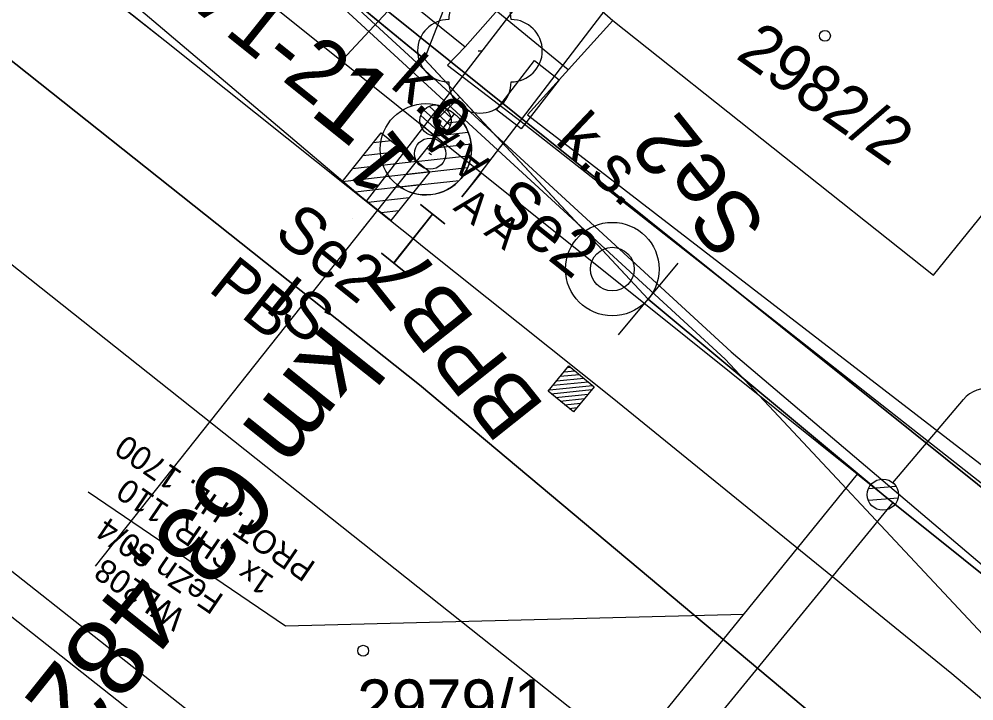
# Model space of a CAD drawing. Extents: x -620537 to -620023, y -1122866 to -1122384.
# Drawn here: x -620241.34 to -620210.72, y -1122748.65 to -1122726.78 of the extents above; entities that cross this region are included whole.
import ezdxf

# ---------------------------------------------------------------- set-up
doc = ezdxf.new("R2010")
doc.units = 0
for name, color, linetype in [('060603_ROZVODY_NN', 7, 'Continuous'), ('060604_ROZVODY_SEE', 7, 'Continuous'), ('CETIN', 7, 'Continuous'), ('POPIS KABELOVÉ TRASY', 7, 'Continuous'), ('PS 06-14-01_trasa_sdělovací_nové', 7, 'Continuous'), ('SEE', 7, 'Continuous'), ('SSZT', 7, 'Continuous'), ('SSZT-DK', 7, 'Continuous'), ('SSZT-TK', 7, 'Continuous'), ('STÁVAJÍCÍ STOŽÁRY ODHAD', 7, 'Continuous'), ('UZEMNĚNÍ', 7, 'Continuous'), ('Vrstva 1', 7, 'Continuous'), ('Vrstva 16', 7, 'Continuous'), ('Vrstva 2', 7, 'Continuous'), ('Vrstva 27', 7, 'Continuous'), ('Vrstva 3', 7, 'Continuous'), ('Vrstva 36', 7, 'Continuous'), ('Vrstva 50', 7, 'Continuous'), ('Vrstva 53', 7, 'Continuous'), ('Vrstva 55', 7, 'Continuous'), ('Vrstva 56', 7, 'Continuous'), ('Vrstva 57', 7, 'Continuous'), ('Vrstva 6', 7, 'Continuous'), ('Vrstva 62', 7, 'Continuous'), ('ČD-T', 7, 'Continuous')]:
    doc.layers.add(name, color=color, linetype=linetype)

msp = doc.modelspace()

# ---------------------------------------------------------------- linework, layer by layer
at = {"layer": '060603_ROZVODY_NN'}
msp.add_lwpolyline([(-620240.174, -1122718.342), (-620228.339, -1122728.069), (-620221.166, -1122735.76), (-620213.633, -1122742.038), (-620205.954, -1122748.188), (-620177.512, -1122774.524), (-620185.522, -1122781.049), (-620181.59, -1122785.57), (-620173.131, -1122796.401), (-620158.909, -1122820.61), (-620158.907, -1122820.615)], dxfattribs=at)
at = {"layer": '060604_ROZVODY_SEE'}
msp.add_lwpolyline([(-620176.843, -1122775.143), (-620205.954, -1122748.188), (-620213.633, -1122742.038), (-620221.166, -1122735.76), (-620228.339, -1122728.069), (-620234.256, -1122723.205), (-620240.174, -1122718.342), (-620248.298, -1122711.665), (-620253.571, -1122707.331), (-620257.271, -1122704.364), (-620247.325, -1122692.032), (-620244.518, -1122694.296)], dxfattribs=at)
at = {"layer": 'CETIN'}
for points in [[(-620281.95, -1122736.09), (-620279.78, -1122731.91), (-620278.12, -1122730.04), (-620275.23, -1122726.8), (-620267.96, -1122716.51), (-620253.8, -1122706.08), (-620234.3, -1122721.82), (-620227.04, -1122727.67)], [(-620227.04, -1122727.67), (-620224.61, -1122724.91)], [(-620227.04, -1122727.67), (-620227.6, -1122728.26), (-620225.24, -1122730.07), (-620192.39, -1122755.87), (-620182.03, -1122766.47), (-620178.55, -1122770.03), (-620178.11, -1122770.48), (-620151.688, -1122809.986)]]:
    msp.add_lwpolyline(points, dxfattribs=at)
at = {"layer": 'POPIS KABELOVÉ TRASY'}
msp.add_line((-620239.125, -1122741.959), (-620239.125, -1122741.959), dxfattribs=at)
msp.add_line((-620239.125, -1122741.959), (-620239.125, -1122741.959), dxfattribs=at)
for points in [[(-620228.339, -1122728.069), (-620218.049, -1122701.604), (-620224.371, -1122697.311)], [(-620218.104, -1122745.872), (-620232.802, -1122746.253), (-620239.125, -1122741.959)]]:
    msp.add_lwpolyline(points, dxfattribs=at)
at = {"layer": 'PS 06-14-01_trasa_sdělovací_nové'}
msp.add_lwpolyline([(-620232.134, -1122718.841), (-620235.045, -1122722.562), (-620243.025, -1122715.998), (-620248.321, -1122722.765), (-620228.504, -1122738.508), (-620211.634, -1122752.654), (-620198.933, -1122763.626), (-620190.05, -1122772.28), (-620190.33, -1122775.52), (-620181.59, -1122785.57), (-620173.131, -1122796.401), (-620158.909, -1122820.61), (-620158.907, -1122820.615)], dxfattribs=at)
at = {"layer": 'SEE'}
for points in [[(-620257.826, -1122706.644), (-620244.955, -1122716.952), (-620221.313, -1122735.887), (-620205.954, -1122748.188), (-620187.818, -1122764.98), (-620176.843, -1122775.143)], [(-620213.321, -1122742.288), (-620221.898, -1122752.771), (-620210.905, -1122762.159)]]:
    msp.add_lwpolyline(points, dxfattribs=at)
at = {"layer": 'SSZT'}
msp.add_lwpolyline([(-620153.29, -1122812.344), (-620160.216, -1122801.593), (-620175.654, -1122778.856), (-620179.825, -1122771.902), (-620189.291, -1122760.708), (-620207.424, -1122744.252), (-620237.066, -1122720.469), (-620255.602, -1122705.516), (-620251.355, -1122700.201)], dxfattribs=at)
at = {"layer": 'SSZT-DK'}
msp.add_lwpolyline([(-620332.62, -1122702.617), (-620308.772, -1122717.798), (-620291.405, -1122732.208), (-620277.196, -1122744.115), (-620257.608, -1122720.05), (-620250.251, -1122710.721), (-620233.29, -1122724.26), (-620218.699, -1122737.685), (-620210.438, -1122746.518), (-620193.319, -1122761.993), (-620178.352, -1122775.894), (-620171.184, -1122783.621), (-620164.843, -1122792.284), (-620156.695, -1122803.312), (-620151.985, -1122810.422)], dxfattribs=at)
at = {"layer": 'SSZT-TK'}
msp.add_line((-620229.519, -1122726.524), (-620231.426, -1122728.569), dxfattribs=at)
msp.add_lwpolyline([(-620251.547, -1122700.3), (-620255.602, -1122705.516), (-620237.066, -1122720.469), (-620207.424, -1122744.252), (-620189.291, -1122760.708), (-620179.825, -1122771.902), (-620175.654, -1122778.856), (-620160.216, -1122801.593), (-620153.29, -1122812.344)], dxfattribs=at)
at = {"layer": 'STÁVAJÍCÍ STOŽÁRY ODHAD'}
for p, q in [((-620213.319, -1122741.653), (-620211.057, -1122738.981)), ((-620214.101, -1122741.837), (-620213.224, -1122741.764)), ((-620214.106, -1122742.213), (-620213.152, -1122742.134))]:
    msp.add_line(p, q, dxfattribs=at)
msp.add_circle((-620213.642, -1122742.034), 0.5, dxfattribs=at)
msp.add_arc((-620210.294, -1122739.627), 1, 319.7483, 139.7483, dxfattribs=at)
at = {"layer": 'UZEMNĚNÍ'}
msp.add_lwpolyline([(-620221.747, -1122750.368), (-620214.46, -1122741.375), (-620205.954, -1122748.188), (-620176.843, -1122775.143)], dxfattribs=at)
at = {"layer": 'Vrstva 1'}
for p, q in [((-620227.989, -1122730.033), (-620227.205, -1122729.285)), ((-620227.205, -1122729.285), (-620221.166, -1122735.76))]:
    msp.add_line(p, q, dxfattribs=at)
for points in [[(-620307.469, -1122665.582), (-620307.245, -1122665.745), (-620300.366, -1122670.953), (-620293.063, -1122676.601), (-620287.47, -1122681.018), (-620281.24, -1122686.066), (-620276.174, -1122690.251), (-620272.417, -1122693.451), (-620267.757, -1122697.544), (-620266.519, -1122698.689), (-620262.242, -1122702.65), (-620256.103, -1122708.562), (-620249.907, -1122714.621), (-620245.657, -1122718.815), (-620238.557, -1122725.547), (-620230.199, -1122732.623), (-620229.854, -1122732.906)], [(-620310.211, -1122669.621), (-620307.461, -1122671.648), (-620300.906, -1122676.615), (-620294.546, -1122681.556), (-620287.988, -1122686.712), (-620281.909, -1122691.52), (-620277.852, -1122694.735), (-620274.362, -1122697.517), (-620269.944, -1122701.034), (-620263.761, -1122705.928), (-620255.894, -1122712.191), (-620251.107, -1122715.999), (-620247.589, -1122718.79), (-620245.37, -1122720.556), (-620245.065, -1122720.798), (-620243.16, -1122722.318), (-620236.673, -1122727.474), (-620229.854, -1122732.906), (-620228.705, -1122733.823), (-620228.351, -1122734.106), (-620222.324, -1122738.923)], [(-620287.988, -1122686.712), (-620281.909, -1122691.52), (-620277.852, -1122694.735), (-620274.362, -1122697.517), (-620269.944, -1122701.034), (-620263.761, -1122705.928), (-620255.894, -1122712.191), (-620251.107, -1122715.999), (-620247.589, -1122718.79), (-620245.37, -1122720.556), (-620245.065, -1122720.798), (-620243.16, -1122722.318), (-620236.673, -1122727.474), (-620229.854, -1122732.906), (-620228.705, -1122733.823), (-620228.351, -1122734.106), (-620222.324, -1122738.923), (-620215.936, -1122744.099), (-620211.427, -1122747.773), (-620209.034, -1122749.786), (-620203.242, -1122754.772), (-620197.369, -1122760.098), (-620191.907, -1122765.364)], [(-620173.839, -1122795.494), (-620176.67, -1122791.87), (-620181.59, -1122785.57), (-620185.43, -1122781.13), (-620190.33, -1122775.52), (-620190.05, -1122772.28), (-620198.933, -1122763.626), (-620211.634, -1122752.654), (-620228.504, -1122738.508), (-620248.321, -1122722.765)], [(-620235.055, -1122722.549), (-620228.339, -1122728.069), (-620227.205, -1122729.285)]]:
    msp.add_lwpolyline(points, dxfattribs=at)
at = {"layer": 'Vrstva 16'}
msp.add_lwpolyline([(-620223.739, -1122728.414), (-620230.921, -1122722.506), (-620236.041, -1122718.293), (-620237.607, -1122717.084), (-620236.205, -1122715.408), (-620251.701, -1122703.411), (-620251.364, -1122702.889), (-620249.497, -1122700.283), (-620232.51, -1122713.28), (-620235.025, -1122716.425), (-620234.751, -1122716.645), (-620225.938, -1122723.731)], dxfattribs=at)
at = {"layer": 'Vrstva 2'}
for p, q in [((-620227.517, -1122730.191), (-620228.194, -1122729.578)), ((-620227.5, -1122729.937), (-620227.942, -1122729.537)), ((-620227.384, -1122729.816), (-620229.212, -1122732.102)), ((-620227.786, -1122730.488), (-620228.462, -1122729.875)), ((-620227.619, -1122730.369), (-620228.359, -1122729.699)), ((-620228.037, -1122730.529), (-620228.478, -1122730.13)), ((-620227.623, -1122730.111), (-620227.149, -1122730.058)), ((-620227.954, -1122730.526), (-620226.945, -1122730.414)), ((-620228.285, -1122730.94), (-620226.85, -1122730.78)), ((-620228.618, -1122731.354), (-620226.852, -1122731.157)), ((-620228.949, -1122731.768), (-620226.963, -1122731.547)), ((-620229.121, -1122732.165), (-620227.234, -1122731.955)), ((-620229.212, -1122732.102), (-620229.854, -1122732.906)), ((-620229.854, -1122732.906), (-620238.907, -1122744.323)), ((-620222.125, -1122736.913), (-620220.207, -1122734.607)), ((-620223.868, -1122738.095), (-620223.523, -1122738.061)), ((-620223.75, -1122737.951), (-620223.667, -1122737.943)), ((-620224.221, -1122738.526), (-620223.092, -1122738.413)), ((-620224.103, -1122738.382), (-620223.236, -1122738.296)), ((-620223.986, -1122738.238), (-620223.38, -1122738.178)), ((-620224.338, -1122738.669), (-620222.949, -1122738.531)), ((-620224.283, -1122738.796), (-620222.978, -1122738.666)), ((-620224.139, -1122738.913), (-620223.096, -1122738.809)), ((-620223.996, -1122739.031), (-620223.214, -1122738.953)), ((-620223.852, -1122739.148), (-620223.331, -1122739.096)), ((-620223.708, -1122739.266), (-620223.449, -1122739.24))]:
    msp.add_line(p, q, dxfattribs=at)
for points in [[(-620249.907, -1122714.621), (-620245.657, -1122718.815), (-620238.557, -1122725.547), (-620230.199, -1122732.623), (-620229.854, -1122732.906)], [(-620251.107, -1122715.999), (-620247.589, -1122718.79), (-620245.37, -1122720.556), (-620245.065, -1122720.798), (-620243.16, -1122722.318), (-620238.765, -1122725.812), (-620236.673, -1122727.474), (-620229.854, -1122732.906)]]:
    msp.add_lwpolyline(points, dxfattribs=at)
msp.add_lwpolyline([(-620223.713, -1122737.905), (-620222.9, -1122738.571), (-620223.566, -1122739.383), (-620224.378, -1122738.718)], close=True, dxfattribs=at)
msp.add_lwpolyline([(-620223.713, -1122737.905), (-620222.9, -1122738.571), (-620223.566, -1122739.383), (-620224.378, -1122738.718)], close=True, dxfattribs=at)
for centre, radius in [((-620228.298, -1122730.959), 1.464), ((-620227.989, -1122730.033), 0.5), ((-620222.319, -1122734.801), 1.5), ((-620222.319, -1122734.801), 0.7)]:
    msp.add_circle(centre, radius, dxfattribs=at)
msp.add_arc((-620228.298, -1122730.959), 1.463, 231.386, 51.3468, dxfattribs=at)
at = {"layer": 'Vrstva 27'}
msp.add_line((-620228.203, -1122731.073), (-620228.117, -1122731.125), dxfattribs=at)
msp.add_circle((-620228.16, -1122731.099), 0.5, dxfattribs=at)
at = {"layer": 'Vrstva 3'}
for p, q in [((-620230.199, -1122732.623), (-620210.91, -1122707.563)), ((-620229.413, -1122730.691), (-620229.988, -1122730.756)), ((-620228.999, -1122731.022), (-620230.319, -1122731.17)), ((-620228.584, -1122731.353), (-620230.65, -1122731.585)), ((-620228.17, -1122731.684), (-620230.981, -1122731.999)), ((-620228.5, -1122732.098), (-620230.566, -1122732.33)), ((-620228.832, -1122732.513), (-620230.151, -1122732.661)), ((-620229.162, -1122732.927), (-620229.737, -1122732.992)), ((-620228.472, -1122732.73), (-620227.69, -1122733.353)), ((-620227.69, -1122733.354), (-620228.471, -1122732.73)), ((-620228.081, -1122733.041), (-620229.329, -1122734.605)), ((-620229.329, -1122734.604), (-620228.081, -1122733.042)), ((-620228.939, -1122734.916), (-620229.72, -1122734.292)), ((-620229.72, -1122734.293), (-620228.938, -1122734.916))]:
    msp.add_line(p, q, dxfattribs=at)
msp.add_lwpolyline([(-620229.417, -1122733.247), (-620230.981, -1122731.999), (-620229.733, -1122730.436), (-620228.17, -1122731.684)], close=True, dxfattribs=at)
at = {"layer": 'Vrstva 36'}
msp.add_lwpolyline([(-620225.246, -1122730.307), (-620226.036, -1122729.694), (-620224.81, -1122728.113), (-620224.02, -1122728.726), (-620225.246, -1122730.307)], dxfattribs=at)
at = {"layer": 'Vrstva 50'}
msp.add_line((-620226.624, -1122727.801), (-620226.482, -1122727.801), dxfattribs=at)
for centre, start, end in [((-620226.564, -1122726.799), 0, 180), ((-620227.564, -1122727.799), 90, 270), ((-620225.564, -1122727.799), 270, 90), ((-620226.564, -1122728.799), 180, 0)]:
    msp.add_arc(centre, 1, start, end, dxfattribs=at)
at = {"layer": 'Vrstva 53'}
for p, q in [((-620223.68, -1122725.62), (-620222.3, -1122726.83)), ((-620222.3, -1122726.83), (-620225.04, -1122729.85)), ((-620225.04, -1122729.85), (-620205.48, -1122744.93)), ((-620246.12, -1122731.05), (-620221.1, -1122750.9)), ((-620220.43, -1122762.64), (-620252.35, -1122737.47))]:
    msp.add_line(p, q, dxfattribs=at)
at = {"layer": 'Vrstva 55'}
for p, q in [((-620223.68, -1122725.62), (-620222.3, -1122726.83)), ((-620222.3, -1122726.83), (-620225.04, -1122729.85)), ((-620222.3, -1122726.83), (-620212.02, -1122735)), ((-620225.04, -1122729.85), (-620205.48, -1122744.93)), ((-620246.12, -1122731.05), (-620221.1, -1122750.9)), ((-620212.02, -1122735), (-620209.48, -1122731.85)), ((-620220.43, -1122762.64), (-620252.35, -1122737.47))]:
    msp.add_line(p, q, dxfattribs=at)
at = {"layer": 'Vrstva 56'}
msp.add_line((-620225.88, -1122756.88), (-620250.89, -1122737.15), dxfattribs=at)
at = {"layer": 'Vrstva 57'}
for centre in [(-620215.5, -1122727.32), (-620230.31, -1122747.04)]:
    msp.add_circle(centre, 0.175, dxfattribs=at)
at = {"layer": 'Vrstva 6'}
for p, q in [((-620226.831, -1122732.095), (-620209.385, -1122709.263)), ((-620227.143, -1122732.486), (-620226.519, -1122731.704)), ((-620226.519, -1122731.704), (-620227.143, -1122732.486))]:
    msp.add_line(p, q, dxfattribs=at)
at = {"layer": 'Vrstva 62'}
for p, q in [((-620229.734, -1122732.072), (-620229.734, -1122732.072)), ((-620229.418, -1122732.34), (-620229.418, -1122732.34)), ((-620230.659, -1122733.166), (-620230.659, -1122733.166)), ((-620230.307, -1122733.444), (-620230.307, -1122733.444)), ((-620228.274, -1122733.27), (-620228.274, -1122733.27)), ((-620229.185, -1122734.341), (-620229.185, -1122734.341))]:
    msp.add_line(p, q, dxfattribs=at)
at = {"layer": 'ČD-T'}
msp.add_lwpolyline([(-620332.453, -1122702.37), (-620308.585, -1122717.564), (-620291.218, -1122731.973), (-620279.983, -1122741.462), (-620260.482, -1122717.473), (-620252.938, -1122708.192), (-620233.103, -1122724.025), (-620218.511, -1122737.45), (-620206.638, -1122747.527), (-620193.132, -1122761.758), (-620178.165, -1122775.66), (-620170.996, -1122783.386), (-620164.655, -1122792.049), (-620156.507, -1122803.078), (-620151.811, -1122810.167)], dxfattribs=at)

# ---------------------------------------------------------------- texts
at = {"layer": 'POPIS KABELOVÉ TRASY'}
for s, p in [('PROT. HL. 1700', (-620231.789, -1122744.241)), ('1x CHR. 110', (-620233.123, -1122744.695)), ('FeZn 30/4', (-620234.739, -1122745.289)), ('WL208', (-620235.956, -1122745.822))]:
    msp.add_text(s, height=0.75, rotation=145.8181, dxfattribs=at).set_placement(p)
at = {"layer": 'Vrstva 2'}
for s, rotation, p in [('1', 321.3669, (-620232.091, -1122729.792)), ('km 63,482', 231.3669, (-620231.518, -1122736.471))]:
    msp.add_text(s, height=2.5, rotation=rotation, dxfattribs=at).set_placement(p)
at = {"layer": 'Vrstva 27'}
for s, height, rotation, p in [('V1-2', 2, 321.298, (-620236.203, -1122726.112)), ('k.o.', 1.5, 318.5205, (-620229.486, -1122728.932))]:
    msp.add_text(s, height=height, rotation=rotation, dxfattribs=at).set_placement(p)
at = {"layer": 'Vrstva 3'}
for s, height, rotation, p in [('Se2', 2, 128.542, (-620217.295, -1122733.378)), ('1', 2, 128.542, (-620228.524, -1122731.405)), ('PB', 1.5, 321.4071, (-620235.318, -1122735.477)), ('BPB7', 2, 128.542, (-620224.449, -1122739.213)), ('IS', 1.5, 321.4071, (-620233.508, -1122736.093))]:
    msp.add_text(s, height=height, rotation=rotation, dxfattribs=at).set_placement(p)
at = {"layer": 'Vrstva 36'}
msp.add_text('k.s.', height=1.5, rotation=316.4623, dxfattribs=at).set_placement((-620224.191, -1122730.727))
at = {"layer": 'Vrstva 57'}
msp.add_text('2982/2', height=1.5, rotation=324.9, dxfattribs=at).set_placement((-620218.399, -1122728.013))
msp.add_text('2979/1', height=1.5, dxfattribs=at).set_placement((-620230.506, -1122749.46))
at = {"layer": 'Vrstva 6'}
for s, height, rotation, p in [('A A ', 1, 141.3669, (-620226.207, -1122731.314)), ('Se2', 1.5, 321.3669, (-620226.344, -1122732.935)), ('A A ', 1, 321.3669, (-620227.455, -1122732.876)), ('Se2', 1.5, 321.3669, (-620233.225, -1122733.741))]:
    msp.add_text(s, height=height, rotation=rotation, dxfattribs=at).set_placement(p)

doc.saveas('drawing.dxf')
